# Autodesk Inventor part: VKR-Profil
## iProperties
Created: 2001-12
Part Number: VKR-Profil
Material: Steel, Mild
Description: VKR 75x75x5_775
Document SubType Name: Modeling
Designer: Tobben
Control State: 0
Master: False
Checked Out: False
Shininess: 64.0
Length Units: 11269
Angle Units: 11279
Time Units: 11290
Mass Units: 11283
Length Display Precision: 3
Angle Display Precision: 2
Density: 0.0
Volumn: 0.0
Area: 0.0
PropertySet Name: Model Information
Author: Tobben
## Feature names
1. Derived Body1 [Tagging]
